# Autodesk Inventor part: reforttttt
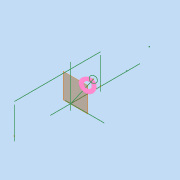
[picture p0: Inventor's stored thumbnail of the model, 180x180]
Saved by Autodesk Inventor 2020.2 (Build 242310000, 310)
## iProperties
Created: 2020-04
Part Number: reforttttt
Material: Générique
Document SubType Name: Modeling
Designer: t.sancier
Density: 1 g/cm^3
Appearance: Rose
Author: t.sancier
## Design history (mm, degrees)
sketch "Esquisse4"
  geometry: C1 r 800 at (0, 0); C2 r 805 at (0, 0); A1 r 800 centre (0, 0) between (-2, 799.997) and (8.981, 799.95) reference; 3 further points
  constraints: 2 centre point, 2 coincident, 1 concentric
  dimensions: "d1" = 800 radius of A1 (derived); "d2" = 1610 diameter of C2 (computed from d1)
extrude "Extrusion1" new body sketch "Esquisse4" stored distance "d3" = 500; taper "d4" = 0 deg
sketch "Esquisse5"
  geometry: C1 r 85 at (0, 0) reference; C2 r 185 at (0, 0); 1 further point
  constraints: 1 centre point, 1 coincident
  dimensions: "d5" = 170 diameter of C1 (derived); "d6" = 370 diameter of C2 (computed from d5)
extrude "Extrusion2" sketch "Esquisse5" stored distance "d7" = 10; taper "d8" = 0 deg
node "Solide1"
node "Référence1"
node "Référence2"
